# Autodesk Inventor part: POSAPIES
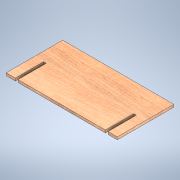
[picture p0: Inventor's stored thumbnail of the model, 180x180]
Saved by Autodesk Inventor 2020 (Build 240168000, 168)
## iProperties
Created: 2020-03
Part Number: POSAPIES
Material: Madera (abedul)
Document SubType Name: Modeling
Designer: Arias
Density: 0.55 g/cm^3
Appearance: Abedul - Natural pulido
Author: Arias
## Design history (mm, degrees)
sketch "Boceto1"
  geometry: L1 (480, 0)-(480, -244); L2 (480, -244)-(0, -244); L3 (0, -244)-(0, 0); L4 (440, 0)-(440, -122); L5 (51.1, 0)-(51.1, -122); L6 (428.9, 0)-(428.9, -122); L7 (40, 0)-(40, -122); L8 (440, -122)-(428.9, -122); L9 (51.1, -122)-(40, -122); L10 (440, 0)-(480, 0); L11 (0, 0)-(40, 0); L12 (51.1, 0)-(428.9, 0)
  constraints: 24 end point, 6 parallel, 6 perpendicular, 4 horizontal, 1 collinear, 1 vertical
  dimensions: "d0" = 480 distance of L1.end L2.end; "d1" = 244 distance of L1.start L1.end; "d2" = 122 distance of L4.start L4.end; "d3" = 122 distance of L5.start L5.end; "d4" = 11.1 distance between parallel lines of L4 L6; "d5" = 11.1 distance between parallel lines of L5 L7; "d6" = 40 distance between parallel lines of L3 L7; "d7" = 400 distance between parallel lines of L7 L4
extrude "Extrusión1" new body sketch "Boceto1" distance "d8" = 11.1; taper "d9" = 0 deg
node "Sólido1"
